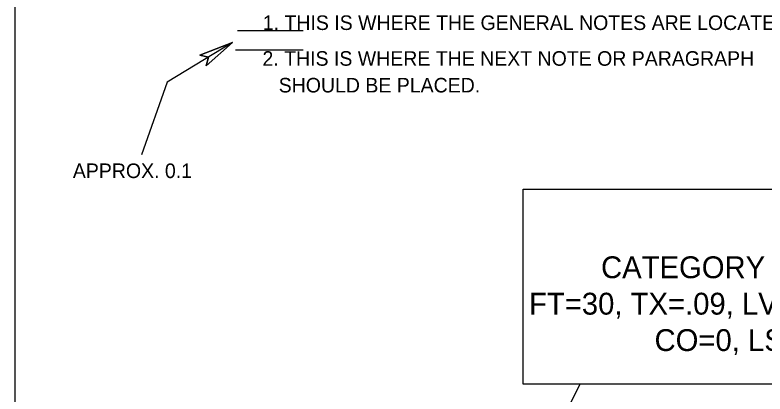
# Model space of a CAD drawing. Extents: x -0.5 to 21.6, y 4.3 to 17.8.
# Drawn here: x 0.394 to 3.481, y 7.7 to 9.261 of the extents above; entities that cross this region are included whole.
import ezdxf

# ---------------------------------------------------------------- set-up
doc = ezdxf.new("R2010")
doc.units = 0
for name, color, linetype in [('DETL-DIMS', 7, 'Continuous'), ('DETL-LINE', 7, 'Continuous'), ('DETL-NOTE', 7, 'Continuous'), ('TTLB-TEXT', 7, 'Continuous'), ('USER-BORD', 7, 'Continuous')]:
    doc.layers.add(name, color=color, linetype=linetype)

msp = doc.modelspace()

# ---------------------------------------------------------------- linework, layer by layer
at = {"layer": 'DETL-DIMS'}
for p, q in [((1.2901, 9.1483), (1.0203, 8.9841)), ((1.2901, 9.1483), (1.1548, 9.0955)), ((1.2901, 9.1483), (1.181, 9.0524)), ((1.1548, 9.0955), (1.191, 9.088)), ((1.191, 9.088), (1.181, 9.0524)), ((1.0203, 8.9841), (0.9148, 8.6849)), ((2.7192, 7.74), (2.4706, 7.2422))]:
    msp.add_line(p, q, dxfattribs=at)
msp.add_lwpolyline([(1.1548, 9.0955), (1.2901, 9.1483), (1.181, 9.0524), (1.191, 9.088)], close=True, dxfattribs=at)
at = {"layer": 'DETL-LINE'}
msp.add_lwpolyline([(0.3943, 14.1527), (0.3943, 16.2906), (7.7685, 16.2906), (7.7685, 5.9375), (0.3943, 5.9375), (0.3943, 13.6862)], dxfattribs=at)
at = {"layer": 'DETL-NOTE'}
for p, q in [((1.3106, 9.1971), (1.5804, 9.1971)), ((1.3018, 9.1171), (1.5804, 9.1171))]:
    msp.add_line(p, q, dxfattribs=at)
at = {"layer": 'TTLB-TEXT'}
msp.add_line((0.3943, 7.3883), (0.3943, 16.2906), dxfattribs=at)
for points in [[(0.3943, 16.2906), (7.7685, 16.2906), (7.7685, 5.9375), (0.3943, 5.9375)], [(2.4865, 8.5442), (4.7055, 8.5442), (4.7055, 7.74), (2.4865, 7.74)]]:
    msp.add_lwpolyline(points, close=True, dxfattribs=at)
at = {"layer": 'USER-BORD'}
msp.add_line((0.3943, 7.3883), (0.3943, 13.6862), dxfattribs=at)

# ---------------------------------------------------------------- texts
at = {"layer": 'DETL-NOTE'}
for s, p in [('1. THIS IS WHERE THE GENERAL NOTES ARE LOCATED.', (1.4142, 9.1994)), ('2. THIS IS WHERE THE NEXT NOTE OR PARAGRAPH', (1.4129, 9.0521)), ('   SHOULD BE PLACED.', (1.4129, 8.9421)), ('APPROX. 0.1', (0.6324, 8.5895))]:
    msp.add_text(s, height=0.06, dxfattribs=at).set_placement(p)
at = {"layer": 'TTLB-TEXT'}
for s, p in [(' CATEGORY CODE ITEMS, ', (2.7731, 8.177)), ('FT=30, TX=.09, LV=13, WT=0,', (2.5102, 8.027)), (' CO=0, LS=.06, IS=.01', (2.9933, 7.877))]:
    msp.add_text(s, height=0.09, dxfattribs=at).set_placement(p)

doc.saveas('drawing.dxf')
